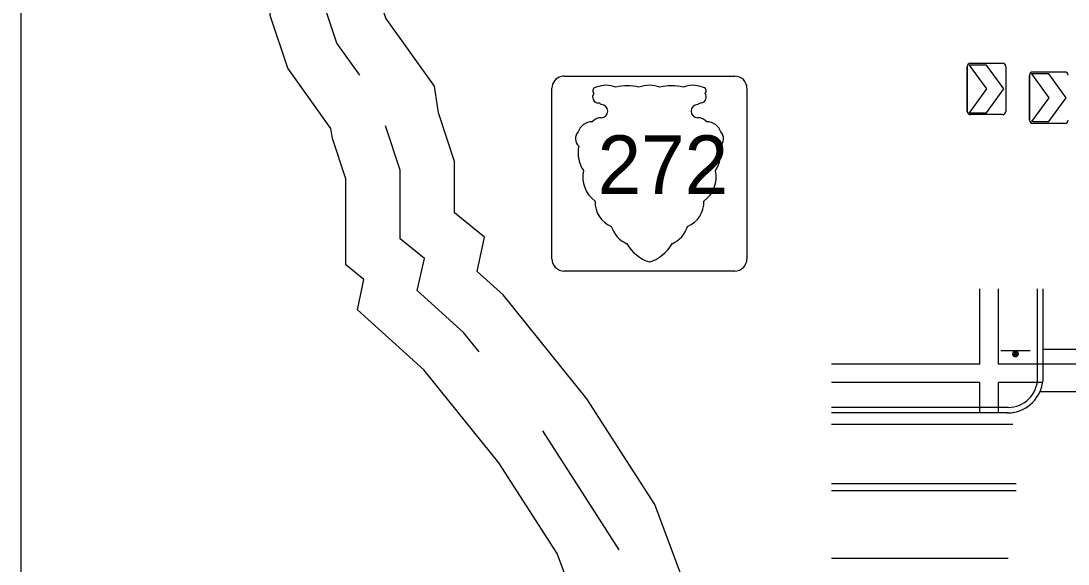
# Model space of a CAD drawing. Extents: x 49991.4 to 50021, y 49987.6 to 50011.4.
# Drawn here: x 50000.336 to 50002.261, y 50006.017 to 50007.015 of the extents above; entities that cross this region are included whole.
import ezdxf

# ---------------------------------------------------------------- set-up
doc = ezdxf.new("R2010")
doc.units = 0
doc.layers.add('Level 1', color=7, linetype='Continuous')
doc.layers.add('Level 10', color=7, linetype='Continuous')

msp = doc.modelspace()

# ---------------------------------------------------------------- linework, layer by layer
at = {"layer": 'Level 1'}
for p, q in [((50002.0756, 50006.8487), (50002.0756, 50006.9315)), ((50002.0756, 50006.8487), (50002.0756, 50006.9315)), ((50002.0756, 50006.9315), (50002.0756, 50006.8487)), ((50002.1111, 50006.9339), (50002.0791, 50006.9339)), ((50002.0791, 50006.9339), (50002.1111, 50006.8901)), ((50002.0816, 50006.9374), (50002.1406, 50006.9374)), ((50002.1431, 50006.8901), (50002.1111, 50006.9339)), ((50002.1466, 50006.9315), (50002.1466, 50006.8487)), ((50002.1961, 50006.9213), (50002.2551, 50006.9213)), ((50001.3345, 50006.9137), (50001.3354, 50006.9137)), ((50001.3354, 50006.9137), (50001.6483, 50006.9137)), ((50002.1902, 50006.8326), (50002.1902, 50006.9153)), ((50002.1902, 50006.8326), (50002.1902, 50006.9153)), ((50002.1902, 50006.9153), (50002.1902, 50006.8326)), ((50002.2256, 50006.9178), (50002.1936, 50006.9178)), ((50002.1936, 50006.9178), (50002.2256, 50006.874)), ((50002.2577, 50006.874), (50002.2256, 50006.9178)), ((50001.312, 50006.5775), (50001.312, 50006.8913)), ((50001.4721, 50006.8931), (50001.472, 50006.8932)), ((50001.6707, 50006.8913), (50001.6707, 50006.5775)), ((50002.1111, 50006.8901), (50002.0791, 50006.8463)), ((50002.1111, 50006.8463), (50002.1431, 50006.8901)), ((50002.2256, 50006.874), (50002.1936, 50006.8302)), ((50002.2256, 50006.8302), (50002.2577, 50006.874)), ((50002.0791, 50006.8463), (50002.1111, 50006.8463)), ((50002.1406, 50006.8429), (50002.0816, 50006.8429)), ((50002.1936, 50006.8302), (50002.2256, 50006.8302)), ((50002.2551, 50006.8268), (50002.1961, 50006.8268)), ((50001.6483, 50006.5552), (50001.3345, 50006.5552)), ((50001.6707, 50006.5552), (50001.6707, 50006.5552)), ((50002.0991, 50006.3843), (50002.0991, 50006.5226)), ((50002.1331, 50006.3842), (50002.1331, 50006.5226)), ((50002.2052, 50006.3589), (50002.2052, 50006.5226)), ((50002.2154, 50006.3603), (50002.2154, 50006.5226)), ((50002.1647, 50006.4083), (50002.1375, 50006.4083)), ((50002.1646, 50006.403), (50002.1646, 50006.403)), ((50002.1915, 50006.4083), (50002.1647, 50006.4083)), ((50002.0991, 50006.3843), (50001.8264, 50006.3843)), ((50002.2154, 50006.3843), (50002.1331, 50006.3843)), ((50002.0991, 50006.3503), (50001.8264, 50006.3503)), ((50002.0991, 50006.2943), (50002.0991, 50006.3502)), ((50002.1331, 50006.2943), (50002.1331, 50006.3503)), ((50002.2141, 50006.3503), (50002.1331, 50006.3503)), ((50002.1508, 50006.3045), (50001.8264, 50006.3045)), ((50002.1493, 50006.2943), (50001.8264, 50006.2943)), ((50002.1603, 50006.2952), (50002.1593, 50006.295)), ((50002.1594, 50006.2731), (50001.8264, 50006.2731)), ((50002.1657, 50006.1643), (50001.8264, 50006.1643)), ((50002.1657, 50006.151), (50001.8264, 50006.151)), ((50001.8264, 50006.0271), (50002.1508, 50006.0271))]:
    msp.add_line(p, q, dxfattribs=at)
msp.add_lwpolyline([(50008.6146, 50011.2628), (50000.3356, 50011.2628), (50000.3356, 50000.0624), (50008.6146, 50000.0624)], close=True, dxfattribs=at)
for points in [[(50001.3799, 50005.8788), (50001.3215, 50006.0357), (50001.2141, 50006.2028), (50001.0765, 50006.3734), (50000.9542, 50006.4839), (50000.9664, 50006.5396), (50000.9328, 50006.5667), (50000.9328, 50006.7245), (50000.9084, 50006.799), (50000.9055, 50006.8175), (50000.8262, 50006.9283), (50000.7939, 50007.0252), (50000.8896, 50007.995)], [(50001.5508, 50005.9931), (50001.5014, 50006.1257), (50001.3765, 50006.32), (50001.2223, 50006.5113), (50001.1745, 50006.5544), (50001.1883, 50006.6177), (50001.1328, 50006.6624), (50001.1328, 50006.7565), (50001.1035, 50006.8459), (50001.0958, 50006.8953), (50001.0064, 50007.0202), (50000.9971, 50007.048), (50001.0691, 50007.7771)], [(50000.9585, 50006.9153), (50000.9163, 50006.9742), (50000.8955, 50007.0366), (50000.9169, 50007.2536)], [(50001.1784, 50006.4064), (50001.1494, 50006.4423), (50001.0643, 50006.5192), (50001.0774, 50006.5786), (50001.0328, 50006.6145), (50001.0328, 50006.7405), (50001.006, 50006.8225)], [(50001.4359, 50006.0427), (50001.2953, 50006.2614)]]:
    msp.add_lwpolyline(points, dxfattribs=at)
for centre, radius, start, end in [((50002.0816, 50006.9315), 0.00591, 90, 180), ((50002.1406, 50006.9315), 0.00591, 0, 90), ((50002.1961, 50006.9153), 0.00591, 90, 180), ((50002.2552, 50006.9153), 0.00591, 0, 90), ((50001.3345, 50006.8913), 0.0224, 103.9917, 180), ((50001.3345, 50006.8913), 0.0224, 90, 103.9917), ((50001.6482, 50006.8913), 0.0224, 0, 90), ((50001.398, 50006.8753), 0.0112, 143.1471, 269.0651), ((50001.3936, 50006.8867), 0.00654, 90.0026, 225.5829), ((50001.4115, 50006.8521), 0.0448, 66.1312, 113.5565), ((50001.451, 50006.8137), 0.0822, 75.186, 105.0796), ((50001.4914, 50006.8465), 0.0504, 90, 112.4922), ((50001.4914, 50006.8465), 0.0504, 67.5078, 90), ((50001.5317, 50006.8137), 0.0822, 74.9204, 104.814), ((50001.5712, 50006.8521), 0.0448, 66.4435, 113.8688), ((50001.5847, 50006.8753), 0.0112, 280.3847, 36.852), ((50001.5891, 50006.8867), 0.00654, 314.4154, 89.9974), ((50001.396, 50006.8549), 0.00934, 44.427, 78.6548), ((50001.4026, 50006.8493), 0.0121, 270, 89.9981), ((50001.5801, 50006.8493), 0.0121, 90, 270), ((50001.5868, 50006.8549), 0.00934, 90, 135.5713), ((50002.0816, 50006.8488), 0.00591, 180, 270), ((50002.1406, 50006.8488), 0.00591, 270, 0), ((50001.3859, 50006.8026), 0.0271, 90, 161.9199), ((50001.4026, 50006.8148), 0.0224, 90, 138.1904), ((50001.5801, 50006.8148), 0.0224, 41.8103, 90), ((50001.5968, 50006.8026), 0.0271, 18.0801, 90.0009), ((50002.1961, 50006.8327), 0.00591, 180, 270), ((50002.2552, 50006.8327), 0.00591, 270, 0), ((50001.3728, 50006.7985), 0.0177, 135.1875, 230.255), ((50001.61, 50006.7985), 0.0177, 309.745, 44.8125), ((50001.4199, 50006.7727), 0.0598, 168.2757, 169.8942), ((50001.5628, 50006.7727), 0.0598, 326.8525, 11.7243), ((50001.4199, 50006.7727), 0.0598, 169.8942, 177.5491), ((50001.4199, 50006.7727), 0.0598, 177.5491, 213.1475), ((50001.4228, 50006.7282), 0.0542, 167.4175, 234.7502), ((50001.56, 50006.7282), 0.0542, 305.2498, 12.5825), ((50001.4391, 50006.6814), 0.0476, 176.9135, 247.903), ((50001.5437, 50006.6814), 0.0476, 292.097, 3.0865), ((50001.4709, 50006.6534), 0.0523, 197.9076, 246.1525), ((50001.5118, 50006.6534), 0.0523, 293.8475, 342.0924), ((50001.5125, 50006.6407), 0.0719, 209.2235, 252.8916), ((50001.4702, 50006.6407), 0.0719, 287.1084, 330.7765), ((50001.3345, 50006.5776), 0.0224, 180, 270), ((50001.6482, 50006.5776), 0.0224, 270, 360), ((50002.1645, 50006.4029), 0.00538, 93.6341, 87.6672), ((50002.1645, 50006.4029), 0.00404, 93.6322, 87.6663), ((50002.1645, 50006.4029), 0.00269, 93.6343, 87.6642), ((50002.1645, 50006.4029), 0.00135, 93.6286, 87.6585), ((50002.1489, 50006.3608), 0.0665, 279.8031, 0), ((50002.1507, 50006.3589), 0.0545, 270, 0), ((50002.1489, 50006.3608), 0.0665, 270, 278.9585)]:
    msp.add_arc(centre, radius, start, end, dxfattribs=at)
at = {"layer": 'Level 10'}
for p, q in [((50002.3427, 50006.4111), (50002.2154, 50006.4111)), ((50002.4706, 50006.3843), (50002.2154, 50006.3843)), ((50002.4762, 50006.3334), (50002.2093, 50006.3334))]:
    msp.add_line(p, q, dxfattribs=at)

# ---------------------------------------------------------------- texts
at = {"layer": 'Level 1'}
msp.add_text('272', height=0.10758, dxfattribs=at).set_placement((50001.396, 50006.6971))

doc.saveas('drawing.dxf')
